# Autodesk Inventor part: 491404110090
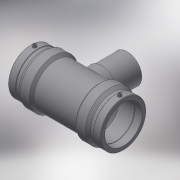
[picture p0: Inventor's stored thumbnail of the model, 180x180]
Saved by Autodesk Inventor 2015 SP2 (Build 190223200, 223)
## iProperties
Created: 2017-06
Part Number: 491404110090
Material: Generic
Description: PLASSON REDUCING TEE 110x90x110
Document SubType Name: Modeling
Designer: KIM
Mass: 1942.35 g
Surface Area: 3001.83 cm^2
Volume: 1942.35 cm^3
Density: 1 g/cm^3
Appearance: Default
Author: KIM
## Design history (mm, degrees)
derived "491404.ipt"
feature "Solid1::491404.ipt"
tag "TaggingFeature1"
body "Solid1"
other parameters: "d0" = 326, "d2" = 143, "d3" = 71, "d4" = 65.2, "d5" = 128.7, "d6" = 104.5, "d8" = 168 deg, "d10" = 28.4, "d11" = 9.46667, "d13" = 326, "d14" = 17.6296, "d17" = 99, "d19" = 3.52592, "d20" = 168 deg, "d22" = 132.99, "d23" = 143, "d25" = 135 deg, "d26" = 228.2, "d29" = 81, "d30" = 15, "d31" = 130.4, "d34" = 5 deg, "d35" = 15, "d39" = 5 deg, "d41" = 4, "d42" = 14, "d43" = 0, "d45" = 4, "d46" = 6, "d47" = 0, "d48" = -147, "d51" = 0, "d52" = 72, "d54" = 0, "d55" = 128.7, "d56" = 143, "d57" = 114.1, "d58" = 135 deg, "d59" = 71, "d60" = 71, "d61" = 135 deg, "d62" = 147, "d72" = 148.33, "d73" = 74.165, "d74" = -147, "d75" = 94.5, "d77" = 0, "d78" = 72, "d80" = 0, "d82" = 75.5, "d83" = 0, "d84" = 3, "d85" = 0, "d86" = 23.66667, "d87" = 130.3302, "d88" = 9.46667, "d89" = 3, "d90" = 0, "L_" = 326, "L_1" = 71, "D_" = 143, "A_" = 81, "d_2" = 12, "H_" = 147
